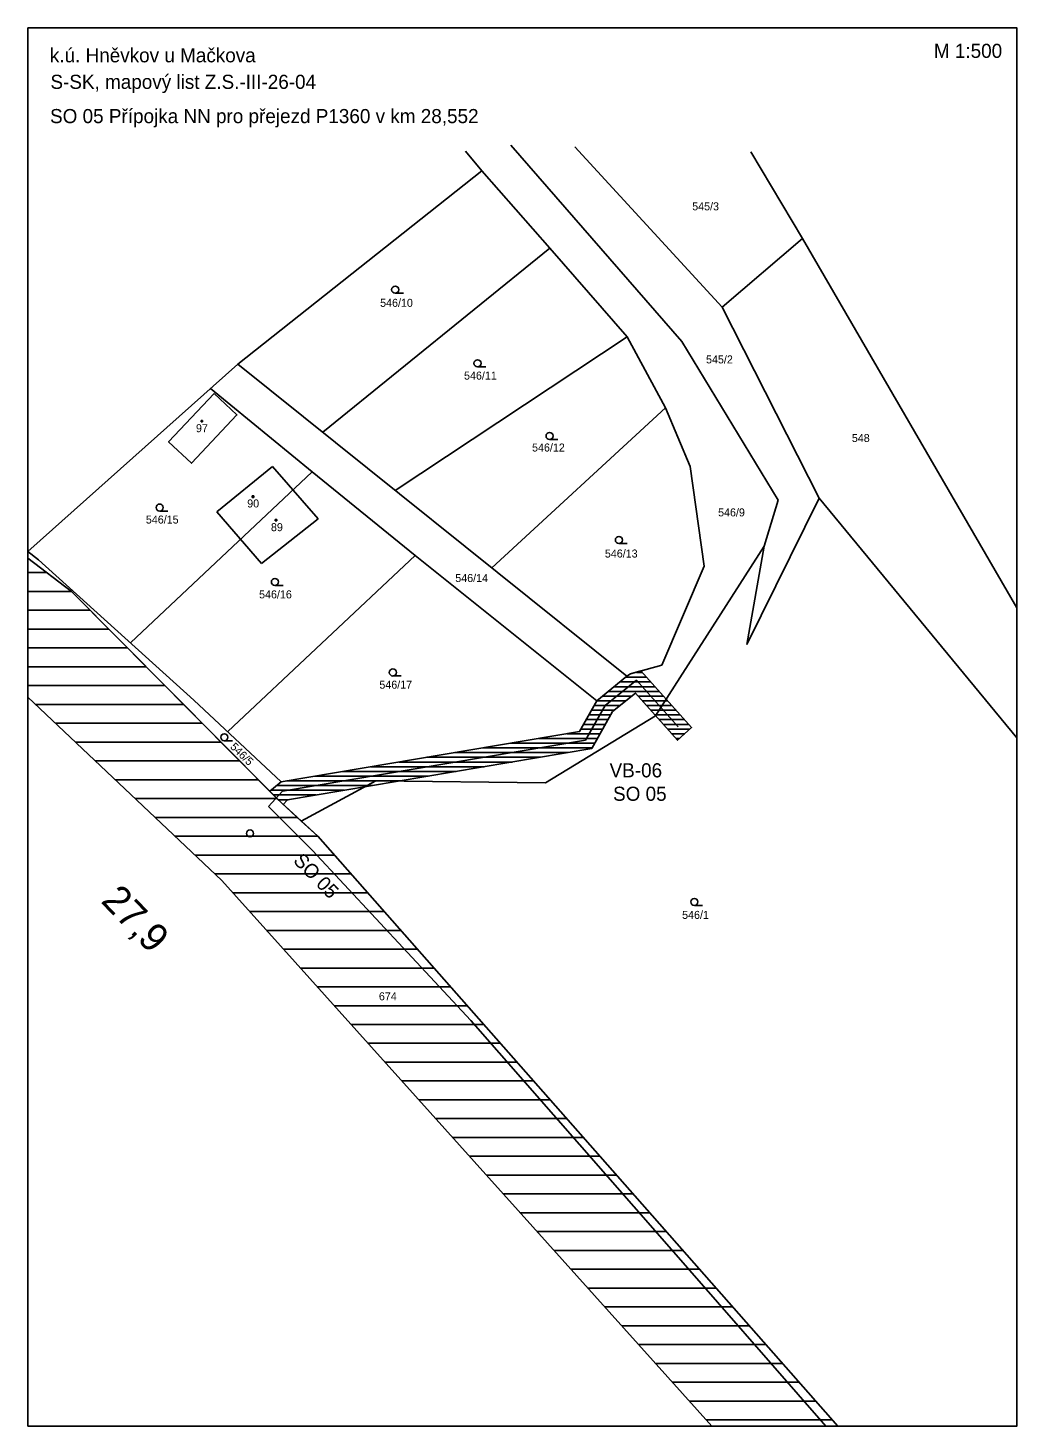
# Model space of a CAD drawing. Extents: x -792659 to -786947, y -1118170 to -1109641.
# Drawn here: x -790184.6 to -790079.6, y -1114003.5 to -1113855 of the extents above; entities that cross this region are included whole.
import ezdxf

# ---------------------------------------------------------------- set-up
doc = ezdxf.new("R2010")
doc.units = 0
doc.layers.add('1', color=7, linetype='Continuous')

# ---------------------------------------------------------------- blocks, each defined once
blk = doc.blocks.new('Z4022')
at = {"layer": '1'}
for p, q in [((-0.1, 0.1), (0.2, 0.1)), ((-0.1, -0.2), (-0.1, 0.1)), ((0.2, 0.1), (0.2, -0.2)), ((0.2, -0.2), (-0.1, -0.2))]:
    blk.add_line(p, q, dxfattribs=at)

msp = doc.modelspace()

# ---------------------------------------------------------------- linework, layer by layer
at = {"layer": '1'}
for p, q in [((-790136.38, -1113870.18), (-790138.11, -1113868.1)), ((-790115.15, -1113888.3), (-790133.3, -1113867.46)), ((-790110.89, -1113884.68), (-790126.52, -1113867.62)), ((-790102.35, -1113877.37), (-790107.85, -1113868.15)), ((-790162.29, -1113890.71), (-790136.38, -1113870.18)), ((-790136.38, -1113870.18), (-790129.18, -1113878.41)), ((-790110.89, -1113884.68), (-790102.35, -1113877.37)), ((-790102.35, -1113877.37), (-790079.58, -1113916.61)), ((-790129.18, -1113878.41), (-790153.26, -1113897.96)), ((-790129.18, -1113878.41), (-790120.98, -1113887.8)), ((-790145.59, -1113883.19), (-790144.71, -1113883.19)), ((-790100.58, -1113904.94), (-790110.89, -1113884.68)), ((-790120.98, -1113887.8), (-790145.58, -1113904.13)), ((-790120.98, -1113887.8), (-790116.88, -1113895.35)), ((-790104.94, -1113905.18), (-790115.15, -1113888.3)), ((-790162.29, -1113890.71), (-790184.58, -1113910.62)), ((-790121, -1113923.86), (-790162.29, -1113890.71)), ((-790136.85, -1113891.01), (-790135.97, -1113891.01)), ((-790154.41, -1113902.14), (-790165.2, -1113893.31)), ((-790116.88, -1113895.35), (-790135.33, -1113912.35)), ((-790116.88, -1113895.35), (-790114.29, -1113901.6)), ((-790129.2, -1113898.73), (-790128.33, -1113898.73)), ((-790154.41, -1113902.14), (-790173.7, -1113920.32)), ((-790158.6, -1113901.58), (-790164.54, -1113906.41)), ((-790153.78, -1113907.15), (-790158.6, -1113901.58)), ((-790143.47, -1113911.03), (-790154.41, -1113902.14)), ((-790114.29, -1113901.6), (-790112.78, -1113912.17)), ((-790108.25, -1113920.48), (-790100.58, -1113904.94)), ((-790106.42, -1113910.07), (-790104.94, -1113905.18)), ((-790100.58, -1113904.94), (-790079.58, -1113930.42)), ((-790170.59, -1113906.32), (-790169.71, -1113906.32)), ((-790164.54, -1113906.41), (-790159.79, -1113911.9)), ((-790159.79, -1113911.9), (-790153.78, -1113907.15)), ((-790121.84, -1113909.77), (-790120.96, -1113909.77)), ((-790117.96, -1113928.08), (-790106.42, -1113910.07)), ((-790117.96, -1113928.08), (-790106.42, -1113910.07)), ((-790106.42, -1113910.07), (-790108.25, -1113920.48)), ((-790184.58, -1113910.61), (-790183.45, -1113911.5)), ((-790179.97, -1113914.86), (-790184.58, -1113911.31)), ((-790184.58, -1113911.31), (-790179.97, -1113914.86)), ((-790166.98, -1113926.4), (-790183.45, -1113911.5)), ((-790163.36, -1113929.73), (-790143.47, -1113911.03)), ((-790143.47, -1113911.03), (-790124.17, -1113926.47)), ((-790184.58, -1113912.86), (-790182.56, -1113912.86)), ((-790117.29, -1113922.69), (-790112.78, -1113912.17)), ((-790158.36, -1113914.23), (-790157.48, -1113914.23)), ((-790184.58, -1113914.86), (-790179.97, -1113914.86)), ((-790158.16, -1113936.84), (-790179.97, -1113914.86)), ((-790179.97, -1113914.86), (-790179.97, -1113914.86)), ((-790179.97, -1113914.86), (-790158.91, -1113936.08)), ((-790184.58, -1113916.86), (-790177.98, -1113916.86)), ((-790184.58, -1113918.86), (-790176, -1113918.86)), ((-790184.58, -1113920.86), (-790174.02, -1113920.86)), ((-790184.58, -1113922.86), (-790172.03, -1113922.86)), ((-790120.6, -1113923.62), (-790121, -1113923.86)), ((-790120.6, -1113923.62), (-790121, -1113923.86)), ((-790117.29, -1113922.69), (-790120.6, -1113923.62)), ((-790117.29, -1113922.69), (-790120.6, -1113923.62)), ((-790119.96, -1113923.48), (-790119.35, -1113923.48)), ((-790119.5, -1113923.31), (-790114.13, -1113929.33)), ((-790184.58, -1113924.86), (-790170.05, -1113924.86)), ((-790145.84, -1113923.84), (-790144.96, -1113923.84)), ((-790124.17, -1113926.47), (-790121, -1113923.86)), ((-790121, -1113923.86), (-790124.17, -1113926.47)), ((-790119.98, -1113924.28), (-790123.3, -1113926.96)), ((-790122.36, -1113924.98), (-790118.01, -1113924.98)), ((-790121.75, -1113924.48), (-790118.46, -1113924.48)), ((-790121.14, -1113923.98), (-790118.9, -1113923.98)), ((-790115.54, -1113929.25), (-790119.98, -1113924.28)), ((-790184.58, -1113926.08), (-790163.98, -1113945.58)), ((-790163.98, -1113945.58), (-790184.58, -1113926.08)), ((-790166.98, -1113926.4), (-790157.71, -1113935.08)), ((-790126.01, -1113929.75), (-790124.17, -1113926.47)), ((-790124.17, -1113926.47), (-790126.01, -1113929.75)), ((-790124.17, -1113926.48), (-790121.1, -1113926.48)), ((-790123.57, -1113925.98), (-790120.48, -1113925.98)), ((-790122.96, -1113925.48), (-790117.57, -1113925.48)), ((-790122.52, -1113927.62), (-790120.09, -1113925.66)), ((-790120.09, -1113925.66), (-790115.62, -1113930.67)), ((-790119.81, -1113925.98), (-790117.12, -1113925.98)), ((-790119.36, -1113926.48), (-790116.67, -1113926.48)), ((-790183.75, -1113926.86), (-790168.06, -1113926.86)), ((-790129.63, -1113935.18), (-790117.96, -1113928.08)), ((-790129.63, -1113935.18), (-790117.96, -1113928.08)), ((-790123.3, -1113926.96), (-790125.37, -1113930.66)), ((-790125.02, -1113927.98), (-790122.72, -1113927.98)), ((-790124.73, -1113927.48), (-790122.34, -1113927.48)), ((-790124.73, -1113931.56), (-790122.52, -1113927.62)), ((-790124.46, -1113926.98), (-790121.72, -1113926.98)), ((-790118.91, -1113926.98), (-790116.23, -1113926.98)), ((-790118.47, -1113927.48), (-790115.78, -1113927.48)), ((-790118.02, -1113927.98), (-790115.34, -1113927.98)), ((-790181.64, -1113928.86), (-790166.08, -1113928.86)), ((-790125.86, -1113929.48), (-790123.56, -1113929.48)), ((-790125.58, -1113928.98), (-790123.28, -1113928.98)), ((-790125.3, -1113928.48), (-790123, -1113928.48)), ((-790117.58, -1113928.48), (-790114.89, -1113928.48)), ((-790117.13, -1113928.98), (-790114.44, -1113928.98)), ((-790116.68, -1113929.48), (-790114.3, -1113929.48)), ((-790115.62, -1113930.67), (-790114.13, -1113929.33)), ((-790179.53, -1113930.86), (-790164.09, -1113930.86)), ((-790163.73, -1113930.73), (-790162.85, -1113930.73)), ((-790157.71, -1113935.08), (-790126.01, -1113929.75)), ((-790126.01, -1113929.75), (-790157.71, -1113935.08)), ((-790125.37, -1113930.66), (-790157.55, -1113936.07)), ((-790133.31, -1113930.98), (-790124.4, -1113930.98)), ((-790130.34, -1113930.48), (-790124.12, -1113930.48)), ((-790127.37, -1113929.98), (-790123.84, -1113929.98)), ((-790116.24, -1113929.98), (-790114.85, -1113929.98)), ((-790115.79, -1113930.48), (-790115.41, -1113930.48)), ((-790157.04, -1113936.99), (-790124.73, -1113931.56)), ((-790142.23, -1113932.48), (-790130.19, -1113932.48)), ((-790139.26, -1113931.98), (-790127.22, -1113931.98)), ((-790136.29, -1113931.48), (-790124.68, -1113931.48)), ((-790177.42, -1113932.86), (-790162.11, -1113932.86)), ((-790151.16, -1113933.98), (-790139.12, -1113933.98)), ((-790148.18, -1113933.48), (-790136.14, -1113933.48)), ((-790145.21, -1113932.98), (-790133.17, -1113932.98)), ((-790175.3, -1113934.86), (-790160.12, -1113934.86)), ((-790158.91, -1113936.08), (-790157.71, -1113935.08)), ((-790157.71, -1113935.08), (-790158.91, -1113936.08)), ((-790158.19, -1113935.48), (-790148.04, -1113935.48)), ((-790157.1, -1113934.98), (-790145.07, -1113934.98)), ((-790155.56, -1113939.25), (-790147.64, -1113934.97)), ((-790155.56, -1113939.25), (-790147.64, -1113934.97)), ((-790154.13, -1113934.48), (-790142.09, -1113934.48)), ((-790147.64, -1113934.97), (-790129.63, -1113935.18)), ((-790147.64, -1113934.97), (-790129.63, -1113935.18)), ((-790173.19, -1113936.86), (-790158.14, -1113936.86)), ((-790157.55, -1113936.07), (-790159.03, -1113937.71)), ((-790158.91, -1113936.08), (-790158.16, -1113936.84)), ((-790158.79, -1113935.98), (-790151.02, -1113935.98)), ((-790158.5, -1113936.48), (-790153.99, -1113936.48)), ((-790158.16, -1113936.84), (-790153.82, -1113940.85)), ((-790158.16, -1113936.84), (-790155.56, -1113939.25)), ((-790157.99, -1113936.98), (-790156.97, -1113936.98)), ((-790157.47, -1113937.48), (-790157.04, -1113936.99)), ((-790159.03, -1113937.71), (-790154.38, -1113942.38)), ((-790171.08, -1113938.86), (-790155.97, -1113938.86)), ((-790155.56, -1113939.25), (-790153.82, -1113940.85)), ((-790168.97, -1113940.86), (-790153.84, -1113940.86)), ((-790098.6, -1114003.51), (-790153.82, -1113940.85)), ((-790153.82, -1113940.85), (-790098.6, -1114003.51)), ((-790166.85, -1113942.86), (-790152.05, -1113942.86)), ((-790154.38, -1113942.38), (-790137.55, -1113960.43)), ((-790164.74, -1113944.86), (-790150.29, -1113944.86)), ((-790163.98, -1113945.58), (-790111.96, -1114003.51)), ((-790111.96, -1114003.51), (-790163.98, -1113945.58)), ((-790162.83, -1113946.86), (-790148.52, -1113946.86)), ((-790161.04, -1113948.86), (-790146.76, -1113948.86)), ((-790113.83, -1113948.22), (-790112.96, -1113948.22)), ((-790159.24, -1113950.86), (-790145, -1113950.86)), ((-790157.44, -1113952.86), (-790143.24, -1113952.86)), ((-790155.65, -1113954.86), (-790141.47, -1113954.86)), ((-790153.85, -1113956.86), (-790139.71, -1113956.86)), ((-790152.06, -1113958.86), (-790137.95, -1113958.86)), ((-790150.26, -1113960.86), (-790136.19, -1113960.86)), ((-790137.55, -1113960.43), (-790117.25, -1113983.63)), ((-790148.46, -1113962.86), (-790134.42, -1113962.86)), ((-790146.67, -1113964.86), (-790132.66, -1113964.86)), ((-790144.87, -1113966.86), (-790130.9, -1113966.86)), ((-790143.08, -1113968.86), (-790129.14, -1113968.86)), ((-790141.28, -1113970.86), (-790127.37, -1113970.86)), ((-790139.48, -1113972.86), (-790125.61, -1113972.86)), ((-790137.69, -1113974.86), (-790123.85, -1113974.86)), ((-790135.89, -1113976.86), (-790122.09, -1113976.86)), ((-790134.1, -1113978.86), (-790120.32, -1113978.86)), ((-790132.3, -1113980.86), (-790118.56, -1113980.86)), ((-790130.51, -1113982.86), (-790116.8, -1113982.86)), ((-790117.25, -1113983.63), (-790099.89, -1114003.51)), ((-790128.71, -1113984.86), (-790115.04, -1113984.86)), ((-790126.91, -1113986.86), (-790113.28, -1113986.86)), ((-790125.12, -1113988.86), (-790111.51, -1113988.86)), ((-790123.32, -1113990.86), (-790109.75, -1113990.86)), ((-790121.53, -1113992.86), (-790107.99, -1113992.86)), ((-790119.73, -1113994.86), (-790106.22, -1113994.86)), ((-790117.93, -1113996.86), (-790104.46, -1113996.86)), ((-790116.14, -1113998.86), (-790102.7, -1113998.86)), ((-790114.34, -1114000.86), (-790100.94, -1114000.86)), ((-790112.55, -1114002.86), (-790099.18, -1114002.86))]:
    msp.add_line(p, q, dxfattribs=at)
for points in [[(-790184.58, -1113855.01), (-790079.58, -1113855.01), (-790079.58, -1114003.51), (-790184.58, -1114003.51)], [(-790164.81, -1113893.84), (-790169.64, -1113898.96), (-790167.23, -1113901.24), (-790162.4, -1113896.11)], [(-790184.58, -1113911.31), (-790179.97, -1113914.86), (-790158.91, -1113936.08), (-790158.16, -1113936.84), (-790155.56, -1113939.25), (-790153.82, -1113940.85), (-790098.6, -1114003.51), (-790111.96, -1114003.51), (-790163.98, -1113945.58), (-790184.58, -1113926.08)], [(-790158.91, -1113936.08), (-790157.71, -1113935.08), (-790126.01, -1113929.75), (-790124.17, -1113926.47), (-790121, -1113923.86), (-790120.6, -1113923.62), (-790119.5, -1113923.31), (-790114.13, -1113929.33), (-790115.62, -1113930.67), (-790120.09, -1113925.66), (-790122.52, -1113927.62), (-790124.73, -1113931.56), (-790157.04, -1113936.99), (-790157.47, -1113937.48)]]:
    msp.add_lwpolyline(points, close=True, dxfattribs=at)
for centre in [(-790145.59, -1113882.81), (-790136.85, -1113890.63), (-790129.2, -1113898.35), (-790170.59, -1113905.95), (-790121.84, -1113909.4), (-790158.36, -1113913.85), (-790145.84, -1113923.47), (-790163.73, -1113930.35), (-790161, -1113940.56), (-790113.83, -1113947.84)]:
    msp.add_circle(centre, 0.375, dxfattribs=at)

# ---------------------------------------------------------------- block references
at = {"layer": '1', "xscale": 0.5, "yscale": 0.5}
for p in [(-790166.13, -1113896.75), (-790160.71, -1113904.77), (-790158.27, -1113907.27)]:
    msp.add_blockref('Z4022', p, dxfattribs=at)

# ---------------------------------------------------------------- texts
at = {"layer": '1'}
for s, height, p in [('M 1:500', 1.5, (-790088.4, -1113858.19)), ('k.ú. Hněvkov u Mačkova', 1.5, (-790182.25, -1113858.66)), ('S-SK, mapový list Z.S.-III-26-04', 1.5, (-790182.19, -1113861.48)), ('SO 05 Přípojka NN pro přejezd P1360 v km 28,552', 1.5, (-790182.23, -1113865.12)), ('545/3', 0.85, (-790114.06, -1113874.38)), ('546/10', 0.85, (-790147.19, -1113884.63)), ('545/2', 0.85, (-790112.59, -1113890.64)), ('546/11', 0.85, (-790138.28, -1113892.36)), ('97', 0.85, (-790166.74, -1113897.95)), ('548', 0.85, (-790097.11, -1113898.99)), ('546/12', 0.85, (-790131.06, -1113900)), ('90', 0.85, (-790161.3, -1113905.94)), ('546/15', 0.85, (-790172.06, -1113907.65)), ('546/9', 0.85, (-790111.31, -1113906.89)), ('89', 0.85, (-790158.78, -1113908.46)), ('546/13', 0.85, (-790123.33, -1113911.26)), ('546/14', 0.85, (-790139.21, -1113913.86)), ('546/16', 0.85, (-790160.04, -1113915.6)), ('546/17', 0.85, (-790147.27, -1113925.19)), ('VB-06', 1.5, (-790122.83, -1113934.61)), ('SO 05', 1.5, (-790122.46, -1113937.1)), ('546/1', 0.85, (-790115.13, -1113949.64)), ('674', 0.85, (-790147.32, -1113958.29))]:
    msp.add_text(s, height=height, dxfattribs=at).set_placement(p)
for s, height, rotation, p in [('546/5', 0.85, 315.534, (-790163.17, -1113931.44)), ('SO 05', 1.5, 314.3926, (-790156.5, -1113943.55)), ('27,9', 3, 313.8969, (-790176.93, -1113947.82))]:
    msp.add_text(s, height=height, rotation=rotation, dxfattribs=at).set_placement(p)

doc.saveas('drawing.dxf')
